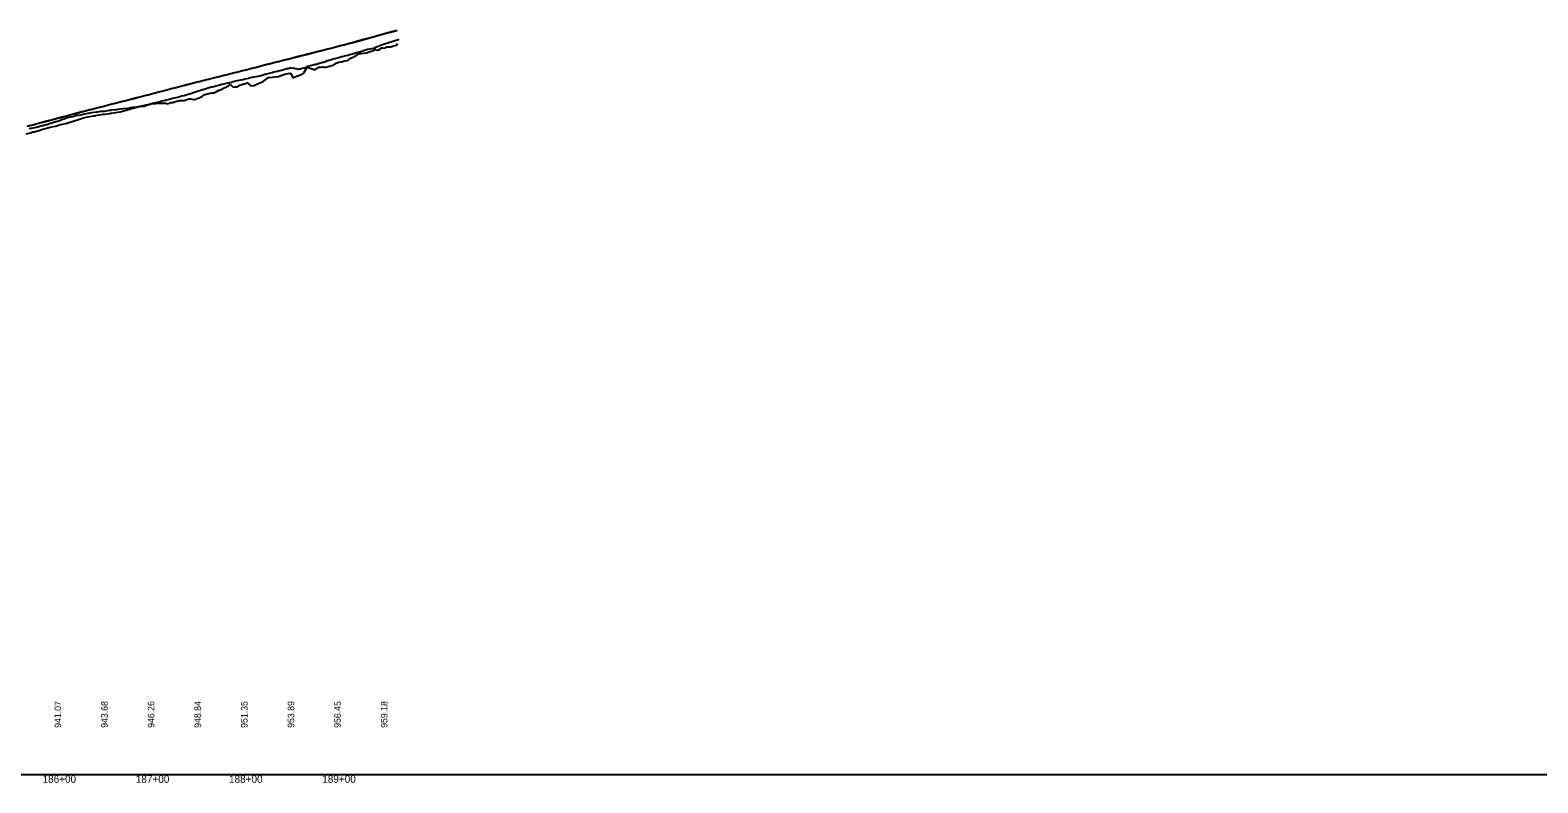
# Model space of a CAD drawing. Extents: x 1475774 to 1484571, y 1098511 to 1113011.
# Drawn here: x 1481337 to 1482954, y 1103502 to 1104310 of the extents above; entities that cross this region are included whole.
import ezdxf

# ---------------------------------------------------------------- set-up
doc = ezdxf.new("R2010")
doc.units = 0
for name, color, linetype in [('RD_DDB_PointTX', 7, 'Continuous'), ('RD_DDB_Profile_EX', 7, 'Continuous'), ('RD_DDB_StaTX', 7, 'Continuous'), ('RD_DDB_StripGrade', 7, 'Continuous'), ('RD_GPK_Profile_Cell', 7, 'Continuous'), ('RD_Sketch2', 7, 'Continuous'), ('RD_Sketch3', 7, 'Continuous')]:
    doc.layers.add(name, color=color, linetype=linetype)

msp = doc.modelspace()

# ---------------------------------------------------------------- linework, layer by layer
at = {"layer": 'RD_DDB_PointTX'}
for points in [[(1481664.4, 1104292), (1481669.4, 1104293.3), (1481674.4, 1104294.5), (1481679.4, 1104295.9), (1481684.4, 1104297.3), (1481689.4, 1104298.7), (1481694.4, 1104300.1), (1481699.4, 1104301.4), (1481704.4, 1104302.8), (1481709.4, 1104304.2), (1481714.4, 1104305.5), (1481719.4, 1104306.9), (1481724.4, 1104308.3), (1481729.4, 1104309.6), (1481730.4, 1104309.9)], [(1481334.4, 1104207.1), (1481339.4, 1104208.4), (1481344.4, 1104209.7), (1481349.4, 1104211), (1481354.4, 1104212.4), (1481359.4, 1104213.7), (1481364.4, 1104215), (1481369.4, 1104216.4), (1481374.4, 1104217.7), (1481379.4, 1104219), (1481384.4, 1104220.3), (1481389.4, 1104221.7), (1481394.4, 1104223), (1481399.4, 1104224.3), (1481404.4, 1104225.6), (1481409.4, 1104226.9), (1481414.4, 1104228.1), (1481419.4, 1104229.4), (1481424.4, 1104230.7), (1481429.4, 1104232), (1481434.4, 1104233.3), (1481439.4, 1104234.5), (1481444.4, 1104235.8), (1481449.4, 1104237.1), (1481454.4, 1104238.4), (1481459.4, 1104239.7), (1481464.4, 1104241), (1481469.4, 1104242.3), (1481474.4, 1104243.6), (1481479.4, 1104244.9), (1481484.4, 1104246.3), (1481489.4, 1104247.5), (1481494.4, 1104248.8), (1481499.4, 1104250.1), (1481504.4, 1104251.4), (1481509.4, 1104252.7), (1481514.4, 1104254), (1481519.4, 1104255.2), (1481524.4, 1104256.5), (1481529.4, 1104257.7), (1481534.4, 1104259), (1481539.4, 1104260.3), (1481544.4, 1104261.5), (1481549.4, 1104262.7), (1481554.4, 1104264), (1481559.4, 1104265.2), (1481564.4, 1104266.5), (1481569.4, 1104267.8), (1481574.4, 1104269.1), (1481579.4, 1104270.3), (1481584.4, 1104271.6), (1481589.4, 1104272.9), (1481594.4, 1104274.2), (1481599.4, 1104275.4), (1481604.4, 1104276.7), (1481609.4, 1104278), (1481614.4, 1104279.2), (1481619.4, 1104280.5), (1481624.4, 1104281.8), (1481629.4, 1104283.1), (1481634.4, 1104284.3), (1481639.4, 1104285.6), (1481644.4, 1104286.9), (1481649.4, 1104288.2), (1481654.4, 1104289.5), (1481659.4, 1104290.7), (1481664.4, 1104292)]]:
    msp.add_lwpolyline(points, dxfattribs=at)
at = {"layer": 'RD_DDB_Profile_EX'}
for points in [[(1481663.5, 1104291.6), (1481668.5, 1104292.9), (1481673.5, 1104294.1), (1481678.5, 1104295.4), (1481683.5, 1104296.8), (1481688.5, 1104298.2), (1481693.5, 1104299.6), (1481698.5, 1104301), (1481703.5, 1104302.3), (1481708.5, 1104303.7), (1481713.5, 1104305.1), (1481718.5, 1104306.5), (1481723.5, 1104307.8), (1481728.5, 1104309.2), (1481730.4, 1104309.7)], [(1481333.5, 1104206.7), (1481338.5, 1104208), (1481343.5, 1104209.3), (1481348.5, 1104210.6), (1481353.5, 1104211.9), (1481358.5, 1104213.3), (1481363.5, 1104214.6), (1481368.5, 1104215.9), (1481373.5, 1104217.3), (1481378.5, 1104218.6), (1481383.5, 1104219.9), (1481388.5, 1104221.2), (1481393.5, 1104222.6), (1481398.5, 1104223.9), (1481403.5, 1104225.2), (1481408.5, 1104226.5), (1481413.5, 1104227.7), (1481418.5, 1104229), (1481423.5, 1104230.3), (1481428.5, 1104231.6), (1481433.5, 1104232.8), (1481438.5, 1104234.1), (1481443.5, 1104235.4), (1481448.5, 1104236.7), (1481453.5, 1104238), (1481458.5, 1104239.3), (1481463.5, 1104240.6), (1481468.5, 1104241.9), (1481473.5, 1104243.2), (1481478.5, 1104244.5), (1481483.5, 1104245.8), (1481488.5, 1104247.1), (1481493.5, 1104248.4), (1481498.5, 1104249.7), (1481503.5, 1104251), (1481508.5, 1104252.3), (1481513.5, 1104253.6), (1481518.5, 1104254.8), (1481523.5, 1104256.1), (1481528.5, 1104257.3), (1481533.5, 1104258.6), (1481538.5, 1104259.8), (1481543.5, 1104261.1), (1481548.5, 1104262.3), (1481553.5, 1104263.6), (1481558.5, 1104264.8), (1481563.5, 1104266.1), (1481568.5, 1104267.4), (1481573.5, 1104268.6), (1481578.5, 1104269.9), (1481583.5, 1104271.2), (1481588.5, 1104272.5), (1481593.5, 1104273.8), (1481598.5, 1104275), (1481603.5, 1104276.3), (1481608.5, 1104277.6), (1481613.5, 1104278.8), (1481618.5, 1104280.1), (1481623.5, 1104281.4), (1481628.5, 1104282.6), (1481633.5, 1104283.9), (1481638.5, 1104285.2), (1481643.5, 1104286.5), (1481648.5, 1104287.8), (1481653.5, 1104289.1), (1481658.5, 1104290.3), (1481663.5, 1104291.6)]]:
    msp.add_lwpolyline(points, dxfattribs=at)
at = {"layer": 'RD_GPK_Profile_Cell'}
msp.add_line((1477571, 1103511.2), (1484571, 1103511.2), dxfattribs=at)
at = {"layer": 'RD_Sketch2'}
msp.add_lwpolyline([(1481335.9, 1104204.2), (1481337.7, 1104204.7), (1481338.5, 1104204.8), (1481340.1, 1104205), (1481341.9, 1104205.4), (1481343.3, 1104205.8), (1481344.1, 1104206.1), (1481345.1, 1104206.3), (1481346.2, 1104206.6), (1481347.1, 1104206.7), (1481348.4, 1104207.1), (1481350.1, 1104207.5), (1481350.8, 1104207.7), (1481351.3, 1104207.9), (1481352.9, 1104208.2), (1481354.8, 1104208.7), (1481355.1, 1104208.8), (1481358.3, 1104210), (1481360.1, 1104210.5), (1481361.2, 1104210.8), (1481362, 1104211), (1481363.4, 1104211.5), (1481364.1, 1104211.7), (1481365.2, 1104212), (1481365.8, 1104212.1), (1481367.6, 1104212.7), (1481369.5, 1104213.4), (1481370.2, 1104213.6), (1481371.9, 1104214.3), (1481373.2, 1104214.6), (1481375.2, 1104215.4), (1481377, 1104216.1), (1481378.4, 1104216.5), (1481380.7, 1104217), (1481382.6, 1104217.3), (1481384.4, 1104217.9), (1481384.8, 1104218.1), (1481385.3, 1104218.2), (1481386.9, 1104218.8), (1481388.2, 1104218.7), (1481389.1, 1104218.7), (1481389.8, 1104218.8), (1481393, 1104219.4), (1481393.7, 1104219.7), (1481399.2, 1104220.8), (1481399.6, 1104220.8), (1481402.6, 1104221.4), (1481408.4, 1104222.3), (1481409.2, 1104222.3), (1481412.7, 1104223), (1481415.4, 1104223.1), (1481416.4, 1104223.1), (1481421.9, 1104224), (1481423.1, 1104224.1), (1481423.9, 1104224.3), (1481428.3, 1104224.6), (1481429.4, 1104224.7), (1481433.5, 1104225.4), (1481436.4, 1104225.7), (1481437.1, 1104225.8), (1481441.1, 1104226.2), (1481443.2, 1104226.5), (1481444.5, 1104226.7), (1481447, 1104227.1), (1481447.8, 1104227.2), (1481449.2, 1104227.2), (1481451.2, 1104227.6), (1481453, 1104227.9), (1481454.6, 1104228), (1481458, 1104228.2), (1481459, 1104228.3), (1481459.4, 1104228.4), (1481461.6, 1104229.3), (1481464.7, 1104230.1), (1481465.6, 1104230.4), (1481468.1, 1104231), (1481471.5, 1104231.3), (1481474.9, 1104231.6), (1481475.7, 1104231.7), (1481476.6, 1104231.7), (1481478.4, 1104231.6), (1481480.5, 1104231.7), (1481481, 1104231.8), (1481481.6, 1104231.6), (1481484.6, 1104230.8), (1481485, 1104231), (1481486.5, 1104231.6), (1481487.6, 1104232.1), (1481488.4, 1104232.2), (1481490.1, 1104232.4), (1481491.8, 1104232.8), (1481495.1, 1104233.9), (1481497, 1104234.3), (1481498.5, 1104234.5), (1481501.3, 1104234.5), (1481502.1, 1104234.5), (1481505.3, 1104235.6), (1481505.6, 1104235.8), (1481507.6, 1104236.2), (1481508.7, 1104236.3), (1481509.1, 1104236.1), (1481512.1, 1104235.6), (1481512.7, 1104235.6), (1481515.4, 1104236.3), (1481516.1, 1104236.5), (1481518.2, 1104237.1), (1481518.8, 1104237.5), (1481521.7, 1104239.2), (1481522.2, 1104239.6), (1481523.4, 1104240.5), (1481525.5, 1104241.1), (1481526.5, 1104241.4), (1481528.3, 1104241.9), (1481528.9, 1104242), (1481531.4, 1104242.5), (1481532.3, 1104242.6), (1481533.8, 1104242.7), (1481534.6, 1104242.9), (1481535.7, 1104243.5), (1481539.1, 1104245.3), (1481540, 1104245.5), (1481540.9, 1104245.7), (1481542.4, 1104246.6), (1481544.2, 1104247.6), (1481545.8, 1104248.2), (1481549.4, 1104250), (1481551.3, 1104251.4), (1481551.7, 1104251.3), (1481552.6, 1104250.5), (1481554.4, 1104248.8), (1481555.9, 1104249.2), (1481558.9, 1104248.9), (1481559.3, 1104249.2), (1481561.6, 1104251), (1481562.7, 1104251.3), (1481566.1, 1104252.2), (1481566.7, 1104252.4), (1481569.5, 1104253.5), (1481572.8, 1104250.8), (1481573.5, 1104250.3), (1481576.2, 1104250.5), (1481577.2, 1104250.5), (1481579.9, 1104251.9), (1481583, 1104253.2), (1481586.6, 1104254.6), (1481589.7, 1104257), (1481592.4, 1104259), (1481593.1, 1104259.1), (1481596.5, 1104259.4), (1481599.9, 1104259.8), (1481602.4, 1104260), (1481603.2, 1104260.3), (1481606.6, 1104261.4), (1481610, 1104262.5), (1481611.9, 1104263.1), (1481613.4, 1104263.4), (1481616.2, 1104263.8), (1481616.8, 1104262.5), (1481618.4, 1104258.7), (1481620.1, 1104259.4), (1481623.5, 1104260.7), (1481626.9, 1104262), (1481629.6, 1104263.2), (1481630.3, 1104264.2), (1481633.9, 1104270), (1481637, 1104269), (1481640.4, 1104268), (1481642.5, 1104267.4), (1481643.8, 1104268.2), (1481646.5, 1104270), (1481647.2, 1104270.2), (1481649.1, 1104270.3), (1481650.6, 1104270.5), (1481651.7, 1104270.3), (1481653.9, 1104270.2), (1481656.3, 1104270.8), (1481657.5, 1104271.3), (1481658, 1104271.2), (1481660.7, 1104271.8), (1481663.3, 1104273.4), (1481664.1, 1104273.8), (1481664.4, 1104274.1), (1481667.4, 1104275.7), (1481670.4, 1104275.9), (1481670.8, 1104276), (1481673.8, 1104276.9), (1481674.2, 1104276.9), (1481677.6, 1104277.4), (1481680.5, 1104279.7), (1481680.9, 1104279.9), (1481683.9, 1104281.2), (1481684.3, 1104281.5), (1481687.7, 1104283.5), (1481688.6, 1104284), (1481690.4, 1104284.6), (1481691.1, 1104284.7), (1481694.5, 1104285.1), (1481697.1, 1104285.4), (1481697.8, 1104285.6), (1481699.3, 1104286.3), (1481701.2, 1104286.8), (1481703.6, 1104287.5), (1481703.9, 1104287.6), (1481704.6, 1104288), (1481706.7, 1104289.2), (1481708, 1104288.9), (1481709.7, 1104288.5), (1481710.3, 1104288.6), (1481710.7, 1104288.8), (1481711.3, 1104289.2), (1481714, 1104291), (1481714.7, 1104290.8), (1481716, 1104290.5), (1481717.6, 1104290.8), (1481718.1, 1104291.2), (1481719.2, 1104292), (1481721.5, 1104291.8), (1481722.2, 1104291.8), (1481723.3, 1104291.9), (1481724.5, 1104292.2), (1481724.9, 1104292.4), (1481726.4, 1104293.2), (1481728.4, 1104293.3), (1481730.2, 1104293.9), (1481730.7, 1104295.5)], dxfattribs=at)
at = {"layer": 'RD_Sketch3'}
msp.add_lwpolyline([(1481332.6, 1104198.5), (1481338.5, 1104200.2), (1481339.8, 1104200.6), (1481341, 1104200.9), (1481346.6, 1104202.3), (1481348.1, 1104202.8), (1481349, 1104203.1), (1481350.3, 1104203.5), (1481351.3, 1104203.8), (1481352, 1104204), (1481358.3, 1104205.6), (1481360.1, 1104206), (1481364.1, 1104207), (1481365.5, 1104207.3), (1481366.7, 1104207.8), (1481368.4, 1104208.1), (1481374.7, 1104209.6), (1481375.8, 1104209.9), (1481377, 1104210.2), (1481378.2, 1104210.7), (1481383.9, 1104212.7), (1481385.4, 1104213.1), (1481387.5, 1104213.5), (1481389.8, 1104214.2), (1481392.8, 1104215.3), (1481394.2, 1104215.9), (1481395.6, 1104216.3), (1481396.8, 1104216.5), (1481398.6, 1104217), (1481402.6, 1104217.6), (1481404.7, 1104217.9), (1481405.8, 1104218), (1481406.9, 1104218.3), (1481408.4, 1104218.6), (1481415.4, 1104219.6), (1481416.1, 1104219.6), (1481417, 1104219.8), (1481422.3, 1104220.6), (1481423.2, 1104220.8), (1481423.8, 1104220.9), (1481428.3, 1104221.6), (1481433.2, 1104222.4), (1481439.7, 1104224), (1481441.1, 1104224.4), (1481441.9, 1104224.6), (1481443.3, 1104225), (1481444.5, 1104225.4), (1481447.8, 1104226.3), (1481451.2, 1104227.3), (1481452, 1104227.5), (1481454.6, 1104228.2), (1481457.1, 1104228.8), (1481458, 1104229), (1481459.7, 1104229.4), (1481461.4, 1104229.8), (1481464.7, 1104230.5), (1481465.6, 1104230.7), (1481467, 1104231.1), (1481468.1, 1104231.4), (1481471.5, 1104232.2), (1481474.9, 1104233), (1481477, 1104233.6), (1481478.2, 1104233.9), (1481481.8, 1104234.7), (1481482.2, 1104234.8), (1481483, 1104235.1), (1481485, 1104235.6), (1481488.4, 1104236.4), (1481491.8, 1104237.2), (1481493.5, 1104237.6), (1481495.1, 1104238.1), (1481498.5, 1104239.2), (1481499.3, 1104239.4), (1481500, 1104239.3), (1481501.9, 1104239.9), (1481505.3, 1104240.9), (1481508.9, 1104241.9), (1481509.2, 1104242), (1481512, 1104242.9), (1481515.4, 1104244.1), (1481517.2, 1104244.6), (1481518.8, 1104245.2), (1481521.4, 1104246.1), (1481522.2, 1104246.3), (1481525.5, 1104247.4), (1481527.6, 1104248.1), (1481528.9, 1104248.5), (1481531, 1104249.1), (1481532.3, 1104249.2), (1481533.7, 1104249.4), (1481535.8, 1104250), (1481539.1, 1104251), (1481541.5, 1104251.6), (1481542.4, 1104251.9), (1481544.6, 1104252.4), (1481545.8, 1104252.7), (1481548.4, 1104253.3), (1481549.2, 1104253.5), (1481552.6, 1104254.2), (1481554.7, 1104254.7), (1481555.9, 1104255), (1481559.3, 1104255.7), (1481562.9, 1104256.4), (1481565.2, 1104257), (1481566.1, 1104257.2), (1481567.1, 1104257.5), (1481569.5, 1104258.1), (1481571, 1104258.5), (1481572.8, 1104259), (1481575.3, 1104259.6), (1481576.2, 1104259.7), (1481579.6, 1104260.1), (1481583, 1104261), (1481586.4, 1104262.1), (1481588.2, 1104262.7), (1481589.7, 1104262.7), (1481593.2, 1104263.7), (1481596.5, 1104264.6), (1481597, 1104264.8), (1481598.2, 1104265), (1481599.9, 1104265.5), (1481602.1, 1104266), (1481603.2, 1104266.3), (1481606.6, 1104267.1), (1481608.7, 1104267.6), (1481610, 1104268), (1481611, 1104268.3), (1481611.7, 1104268.6), (1481612.3, 1104268.6), (1481613.4, 1104268.9), (1481614.8, 1104269.3), (1481616.2, 1104269.6), (1481616.8, 1104269.6), (1481618.9, 1104269.2), (1481620.1, 1104269), (1481623.5, 1104268.4), (1481624, 1104268.1), (1481624.9, 1104267.9), (1481625.7, 1104268.3), (1481626.9, 1104268.3), (1481628.5, 1104269), (1481630.3, 1104269.3), (1481631, 1104269.5), (1481632.1, 1104269.8), (1481633.6, 1104270.6), (1481634.6, 1104271.1), (1481637, 1104271.8), (1481639.1, 1104272.3), (1481640.4, 1104272.7), (1481642.4, 1104273.4), (1481643.8, 1104273.5), (1481644.3, 1104273.5), (1481646.5, 1104274.4), (1481647.2, 1104274.6), (1481649.8, 1104275.2), (1481650.5, 1104275.4), (1481652, 1104275.7), (1481653.4, 1104276.2), (1481653.9, 1104276.4), (1481655.9, 1104277.2), (1481656.4, 1104277.3), (1481657.3, 1104277.6), (1481659.4, 1104278.2), (1481659.8, 1104278.3), (1481660.7, 1104278.6), (1481664.1, 1104279.5), (1481667.4, 1104280.5), (1481668.1, 1104280.7), (1481668.9, 1104281), (1481669.5, 1104281.2), (1481669.9, 1104281.3), (1481670.8, 1104281.6), (1481673.1, 1104282.1), (1481673.8, 1104282.3), (1481674.2, 1104282.3), (1481677.6, 1104283.2), (1481680.9, 1104284), (1481681.2, 1104284.1), (1481682.4, 1104284.6), (1481683.2, 1104284.7), (1481684.3, 1104285), (1481684.8, 1104285.1), (1481685.6, 1104285.5), (1481686.8, 1104285.8), (1481687.7, 1104286), (1481691.1, 1104287), (1481693.8, 1104287.7), (1481694.5, 1104288), (1481695.5, 1104288.4), (1481695.9, 1104288.6), (1481696.4, 1104288.6), (1481697.8, 1104289), (1481698.6, 1104289.3), (1481699.5, 1104289.5), (1481701.4, 1104290), (1481704.9, 1104290.5), (1481706.2, 1104290.9), (1481706.5, 1104291), (1481708.2, 1104291.9), (1481709, 1104292.5), (1481711.4, 1104293.2), (1481711.8, 1104293.4), (1481712.5, 1104293.7), (1481714.7, 1104294.4), (1481718.1, 1104295.5), (1481720.7, 1104296.4), (1481721.5, 1104296.7), (1481722.1, 1104296.9), (1481724.4, 1104297.5), (1481724.9, 1104297.8), (1481728.2, 1104298.7), (1481731.6, 1104299.7), (1481732, 1104299.8), (1481732.4, 1104299.9), (1481732.7, 1104300.1)], dxfattribs=at)

# ---------------------------------------------------------------- texts
at = {"layer": 'RD_DDB_StaTX'}
for s, p in [('186+00', (1481350.1, 1103502.2)), ('187+00', (1481450.1, 1103502.2)), ('188+00', (1481550.1, 1103502.2)), ('189+00', (1481650.1, 1103502.2))]:
    msp.add_text(s, height=8, dxfattribs=at).set_placement(p)
at = {"layer": 'RD_DDB_StripGrade'}
for s, p in [('941.07', (1481370, 1103561.2)), ('943.68', (1481420, 1103561.2)), ('946.26', (1481470, 1103561.2)), ('948.84', (1481520, 1103561.2)), ('951.35', (1481570, 1103561.2)), ('953.89', (1481620, 1103561.2)), ('956.45', (1481670, 1103561.2)), ('959.18', (1481720, 1103561.2))]:
    msp.add_text(s, height=7, rotation=90, dxfattribs=at).set_placement(p)

doc.saveas('drawing.dxf')
